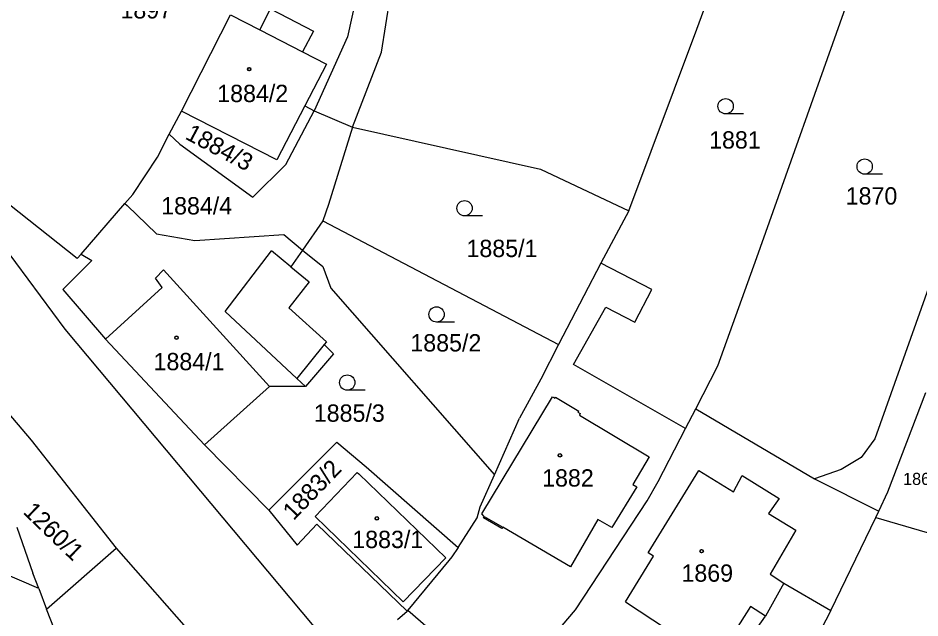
# Model space of a CAD drawing. Extents: x -593183 to -588034, y -1130415 to -1124994.
# Drawn here: x -590543.6 to -590455.2, y -1129144.6 to -1129085.7 of the extents above; entities that cross this region are included whole.
import ezdxf

# ---------------------------------------------------------------- set-up
doc = ezdxf.new("R2010")
doc.units = 0
for name, color, linetype in [('Vrstva 1', 7, 'Continuous'), ('Vrstva 18', 7, 'Continuous'), ('Vrstva 19', 7, 'Continuous'), ('Vrstva 25', 7, 'Continuous'), ('Vrstva 4', 7, 'Continuous')]:
    doc.layers.add(name, color=color, linetype=linetype)

msp = doc.modelspace()

# ---------------------------------------------------------------- linework, layer by layer
at = {"layer": 'Vrstva 1'}
for p, q in [((-590477.07, -1129086.85), (-590470.08, -1129068)), ((-590471.19, -1129109.22), (-590459.59, -1129076.53)), ((-590509.96, -1129081.53), (-590511.29, -1129087.59)), ((-590507.97, -1129089.1), (-590506.83, -1129081.88)), ((-590519.89, -1129086.9), (-590518.83, -1129084.84)), ((-590518.83, -1129084.84), (-590514.63, -1129087.02)), ((-590527.55, -1129094.87), (-590522.75, -1129085.42)), ((-590522.75, -1129085.42), (-590519.89, -1129086.9)), ((-590444.97, -1129085.65), (-590459.63, -1129127.02)), ((-590483.72, -1129104.67), (-590477.07, -1129086.85)), ((-590514.63, -1129087.02), (-590515.69, -1129089.07)), ((-590511.29, -1129087.59), (-590514.54, -1129094.84)), ((-590515.69, -1129089.07), (-590513.36, -1129090.28)), ((-590510.8, -1129096.46), (-590507.97, -1129089.1)), ((-590513.36, -1129090.28), (-590515.47, -1129094.35)), ((-590528.77, -1129097.15), (-590527.55, -1129094.87)), ((-590518.22, -1129099.66), (-590527.55, -1129094.87)), ((-590515.47, -1129094.35), (-590518.22, -1129099.66)), ((-590517.34, -1129100.12), (-590514.54, -1129094.84)), ((-590515.47, -1129094.35), (-590514.54, -1129094.84)), ((-590514.54, -1129094.84), (-590510.8, -1129096.46)), ((-590510.8, -1129096.46), (-590513.16, -1129104.02)), ((-590510.8, -1129096.46), (-590492.39, -1129100.56)), ((-590529.89, -1129099.4), (-590528.77, -1129097.15)), ((-590528.77, -1129097.15), (-590527.7, -1129098.13)), ((-590527.7, -1129098.13), (-590520.56, -1129103.33)), ((-590532.32, -1129103.04), (-590529.89, -1129099.4)), ((-590520.56, -1129103.33), (-590517.34, -1129100.12)), ((-590492.39, -1129100.56), (-590483.72, -1129104.67)), ((-590537.77, -1129109.32), (-590545.38, -1129103.32)), ((-590533.09, -1129103.94), (-590532.32, -1129103.04)), ((-590537.38, -1129108.91), (-590533.09, -1129103.94)), ((-590533.09, -1129103.94), (-590532.88, -1129104.14)), ((-590532.88, -1129104.14), (-590530.01, -1129106.9)), ((-590513.16, -1129104.02), (-590513.69, -1129105.64)), ((-590483.72, -1129104.67), (-590486.48, -1129109.79)), ((-590560.18, -1129106.07), (-590542.27, -1129127.16)), ((-590513.69, -1129105.64), (-590515.7, -1129108.5)), ((-590513.69, -1129105.64), (-590490.6, -1129117.77)), ((-590530.01, -1129106.9), (-590526.24, -1129107.55)), ((-590526.24, -1129107.55), (-590517.54, -1129106.99)), ((-590517.54, -1129106.99), (-590515.7, -1129108.5)), ((-590538.94, -1129116.26), (-590544.98, -1129108.1)), ((-590537.77, -1129109.32), (-590537.38, -1129108.91)), ((-590537.38, -1129108.91), (-590536.34, -1129109.51)), ((-590515.7, -1129108.5), (-590516.85, -1129110.14)), ((-590515.7, -1129108.5), (-590513.72, -1129110.13)), ((-590536.34, -1129109.51), (-590539.18, -1129112.37)), ((-590486.48, -1129109.79), (-590488.13, -1129112.98)), ((-590481.48, -1129112.38), (-590486.48, -1129109.79)), ((-590474.99, -1129119.86), (-590471.19, -1129109.22)), ((-590516.85, -1129110.14), (-590515.04, -1129111.63)), ((-590513.72, -1129110.13), (-590512.93, -1129112.23)), ((-590515.04, -1129111.63), (-590517.03, -1129114.18)), ((-590539.18, -1129112.37), (-590535, -1129117.24)), ((-590512.93, -1129112.23), (-590496.88, -1129130.54)), ((-590483.13, -1129115.57), (-590481.48, -1129112.38)), ((-590488.13, -1129112.98), (-590490.6, -1129117.77)), ((-590517.03, -1129114.18), (-590513.33, -1129117.49)), ((-590489.13, -1129119.72), (-590485.98, -1129114.1)), ((-590485.98, -1129114.1), (-590483.13, -1129115.57)), ((-590508.08, -1129153.16), (-590538.94, -1129116.26)), ((-590535, -1129117.24), (-590525.31, -1129127.6)), ((-590513.33, -1129117.49), (-590513.56, -1129117.78)), ((-590513.56, -1129117.78), (-590512.67, -1129118.67)), ((-590490.6, -1129117.77), (-590492.36, -1129121.16)), ((-590512.67, -1129118.67), (-590515.4, -1129121.87)), ((-590478.16, -1129125.99), (-590489.13, -1129119.72)), ((-590477.17, -1129124.06), (-590474.99, -1129119.86)), ((-590492.36, -1129121.16), (-590494.43, -1129125)), ((-590518.92, -1129121.89), (-590525.31, -1129127.6)), ((-590515.4, -1129121.87), (-590518.92, -1129121.89)), ((-590458.36, -1129132.2), (-590454.62, -1129122.47)), ((-590478.16, -1129125.99), (-590477.17, -1129124.06)), ((-590477.17, -1129124.06), (-590465.55, -1129130.93)), ((-590496.88, -1129130.54), (-590494.43, -1129125)), ((-590480.86, -1129131.19), (-590478.16, -1129125.99)), ((-590542.27, -1129127.16), (-590533.94, -1129137.75)), ((-590519.01, -1129134.01), (-590512.33, -1129127.33)), ((-590512.33, -1129127.33), (-590509.47, -1129129.76)), ((-590459.63, -1129127.02), (-590460.96, -1129128.84)), ((-590525.31, -1129127.6), (-590519.01, -1129134.01)), ((-590460.96, -1129128.84), (-590462.93, -1129130.02)), ((-590509.47, -1129129.76), (-590500.45, -1129137.68)), ((-590462.93, -1129130.02), (-590465.55, -1129130.93)), ((-590541.54, -1129141.7), (-590567.84, -1129130.46)), ((-590514.45, -1129134.62), (-590510.33, -1129130.31)), ((-590510.33, -1129130.31), (-590510.19, -1129130.44)), ((-590510.19, -1129130.44), (-590501.64, -1129138.67)), ((-590498.28, -1129133.7), (-590496.88, -1129130.54)), ((-590465.55, -1129130.93), (-590459.22, -1129134.12)), ((-590481.93, -1129133.11), (-590480.86, -1129131.19)), ((-590459.22, -1129134.12), (-590458.36, -1129132.2)), ((-590498.6, -1129134.76), (-590498.28, -1129133.7)), ((-590488.96, -1129143.78), (-590481.93, -1129133.11)), ((-590519.01, -1129134.01), (-590516.21, -1129137.44)), ((-590505.82, -1129143.01), (-590514.45, -1129134.62)), ((-590459.53, -1129134.72), (-590459.22, -1129134.12)), ((-590516.21, -1129137.44), (-590514.28, -1129135.4)), ((-590514.28, -1129135.4), (-590505.44, -1129143.91)), ((-590500.45, -1129137.68), (-590498.6, -1129134.76)), ((-590463.92, -1129143.86), (-590459.53, -1129134.72)), ((-590459.53, -1129134.72), (-590448.36, -1129138.02)), ((-590543.67, -1129135.67), (-590542.12, -1129140.2)), ((-590540.77, -1129143.71), (-590533.94, -1129137.75)), ((-590533.94, -1129137.75), (-590523.8, -1129149.26)), ((-590500.45, -1129137.68), (-590501.06, -1129138.58)), ((-590501.64, -1129138.67), (-590505.82, -1129143.01)), ((-590501.35, -1129138.94), (-590505.38, -1129143.83)), ((-590501.06, -1129138.58), (-590501.35, -1129138.94)), ((-590541.54, -1129141.7), (-590542.12, -1129140.2)), ((-590541.54, -1129141.7), (-590540.77, -1129143.71)), ((-590468.55, -1129141.16), (-590470.33, -1129144.42)), ((-590468.55, -1129141.16), (-590463.92, -1129143.86)), ((-590539.38, -1129147.31), (-590540.77, -1129143.71)), ((-590505.44, -1129143.91), (-590505.38, -1129143.83)), ((-590505.38, -1129143.83), (-590495.83, -1129152.02)), ((-590494.32, -1129150.07), (-590488.96, -1129143.78)), ((-590463.92, -1129143.86), (-590467.57, -1129150.71)), ((-590472.07, -1129146.86), (-590470.33, -1129144.42))]:
    msp.add_line(p, q, dxfattribs=at)
at = {"layer": 'Vrstva 25'}
for p, q in [((-590472.49, -1129095.15), (-590474.24, -1129095.15)), ((-590458.87, -1129101.06), (-590460.62, -1129101.06)), ((-590498.07, -1129105.15), (-590499.82, -1129105.15)), ((-590500.81, -1129115.56), (-590502.56, -1129115.56)), ((-590509.56, -1129122.25), (-590511.31, -1129122.25))]:
    msp.add_line(p, q, dxfattribs=at)
for centre, radius in [((-590520.92, -1129090.76), 0.175), ((-590520.92, -1129090.76), 0.15), ((-590474.24, -1129094.4), 0.75), ((-590460.62, -1129100.31), 0.75), ((-590499.82, -1129104.4), 0.75), ((-590502.56, -1129114.81), 0.75), ((-590528.04, -1129117.1), 0.175), ((-590528.04, -1129117.1), 0.15), ((-590511.31, -1129121.5), 0.75), ((-590490.48, -1129128.64), 0.175), ((-590490.48, -1129128.64), 0.15), ((-590508.41, -1129134.82), 0.175), ((-590508.41, -1129134.82), 0.15), ((-590476.59, -1129138.03), 0.175), ((-590476.59, -1129138.03), 0.15)]:
    msp.add_circle(centre, radius, dxfattribs=at)
at = {"layer": 'Vrstva 4'}
for p, q in [((-590519.89, -1129086.9), (-590515.69, -1129089.07)), ((-590523.27, -1129114.53), (-590518.74, -1129108.58)), ((-590516.85, -1129110.14), (-590518.74, -1129108.58)), ((-590529.33, -1129110.44), (-590530.11, -1129111.25)), ((-590518.92, -1129121.89), (-590529.33, -1129110.44)), ((-590529.45, -1129112.18), (-590530.11, -1129111.25)), ((-590535, -1129117.24), (-590529.45, -1129112.18)), ((-590516.24, -1129121.09), (-590523.27, -1129114.53)), ((-590513.56, -1129117.78), (-590516.24, -1129121.09)), ((-590516.24, -1129121.09), (-590515.4, -1129121.87)), ((-590498.14, -1129134.36), (-590491.22, -1129122.9)), ((-590491.22, -1129122.9), (-590490.99, -1129123.04)), ((-590490.99, -1129123.04), (-590490.92, -1129122.92)), ((-590490.92, -1129122.92), (-590488.63, -1129124.29)), ((-590488.63, -1129124.29), (-590488.71, -1129124.41)), ((-590488.71, -1129124.41), (-590488.49, -1129124.54)), ((-590488.49, -1129124.54), (-590488.57, -1129124.68)), ((-590488.57, -1129124.68), (-590481.73, -1129128.79)), ((-590481.73, -1129128.79), (-590483.32, -1129131.5)), ((-590481.82, -1129138.21), (-590476.88, -1129130.13)), ((-590476.88, -1129130.13), (-590473.48, -1129132.22)), ((-590473.48, -1129132.22), (-590472.61, -1129130.61)), ((-590472.61, -1129130.61), (-590468.99, -1129132.86)), ((-590482.93, -1129131.73), (-590485.4, -1129135.72)), ((-590483.32, -1129131.5), (-590482.93, -1129131.73)), ((-590468.99, -1129132.86), (-590470.03, -1129134.34)), ((-590497.89, -1129134.64), (-590498.14, -1129134.36)), ((-590497.97, -1129134.76), (-590497.89, -1129134.64)), ((-590497.89, -1129134.64), (-590496.08, -1129135.69)), ((-590470.03, -1129134.34), (-590467.37, -1129135.98)), ((-590496.16, -1129135.82), (-590497.97, -1129134.76)), ((-590486.76, -1129134.93), (-590489.45, -1129139.56)), ((-590485.4, -1129135.72), (-590486.76, -1129134.93)), ((-590496.08, -1129135.69), (-590496.16, -1129135.82)), ((-590489.45, -1129139.56), (-590496.08, -1129135.69)), ((-590467.37, -1129135.98), (-590469.87, -1129140.28)), ((-590484.04, -1129143.01), (-590481.31, -1129138.52)), ((-590481.31, -1129138.52), (-590481.82, -1129138.21)), ((-590469.87, -1129140.28), (-590468.55, -1129141.16)), ((-590484.04, -1129143.01), (-590480.02, -1129145.66)), ((-590471.82, -1129143.47), (-590473.43, -1129146.05)), ((-590470.33, -1129144.42), (-590471.82, -1129143.47)), ((-590506.39, -1129144.75), (-590505.44, -1129143.91))]:
    msp.add_line(p, q, dxfattribs=at)

# ---------------------------------------------------------------- texts
at = {"layer": 'Vrstva 18'}
for s, height, p in [('1897', 1.7, (-590533.53, -1129085.79)), ('1881', 1.7, (-590475.86, -1129098.55)), ('1870', 1.7, (-590462.48, -1129104.04)), ('1884/4', 1.7, (-590529.54, -1129105.01)), ('1885/1', 1.7, (-590499.63, -1129109.19)), ('1885/2', 1.7, (-590505.13, -1129118.45)), ('1885/3', 1.7, (-590514.59, -1129125.34)), ('1867/2', 1.19, (-590456.86, -1129131.54))]:
    msp.add_text(s, height=height, dxfattribs=at).set_placement(p)
for s, rotation, p in [('1884/3', 331.97031, (-590527.29, -1129097.55)), ('1883/2', 46.18116, (-590516.57, -1129135.09)), ('1260/1', 316.02303, (-590543.16, -1129134.27))]:
    msp.add_text(s, height=1.7, rotation=rotation, dxfattribs=at).set_placement(p)
at = {"layer": 'Vrstva 19'}
for s, p in [('1884/2', (-590524.05, -1129093.99)), ('1884/1', (-590530.29, -1129120.29)), ('1882', (-590492.22, -1129131.7)), ('1883/1', (-590510.82, -1129137.73)), ('1869', (-590478.57, -1129141.03))]:
    msp.add_text(s, height=1.7, dxfattribs=at).set_placement(p)

doc.saveas('drawing.dxf')
